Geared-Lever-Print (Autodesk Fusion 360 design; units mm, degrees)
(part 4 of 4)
sketch "Crossblock M3x20 cap head (-70, 1)" plane through (16, 0, 0) normal (1, 0, 0) x axis (0, 0, -1)
  circle C1 centre (-53.5, -70) radius 1.5
extrude "Extrude1" new body sketch "Crossblock M3x20 cap head (-70, 1)" along normal blind 20 bodies "HARDWARE Crossblock M3x20 cap head (-70, 1)"
work_plane "WorkPlane2" AlongDistance 36 ExtraOffset 0
sketch "Button head" plane through (36, 0, 0) normal (1, 0, 0) x axis (0, 0, -1)
  circle C1 centre (-53.5, -70) radius 2.75
extrude "Extrude2" add sketch "Button head" along normal blind 3
work_plane "WorkPlane1" AlongDistance 6.5 ExtraOffset 0
sketch "Rotor clamp M3x16 cap head" plane through (0, 6.5, 0) normal (0, 1, 0) x axis (1, 0, 0)
  circle C1 centre (0, -65) radius 1.5
extrude "Extrude1" new body sketch "Rotor clamp M3x16 cap head" along normal blind 16 bodies "HARDWARE Rotor clamp M3x16 cap head"
work_plane "WorkPlane2" AlongDistance 22.5 ExtraOffset 0
sketch "Button head" plane through (0, 22.5, 0) normal (0, 1, 0) x axis (1, 0, 0)
  circle C1 centre (0, -65) radius 2.75
extrude "Extrude2" add sketch "Button head" along normal blind 3
work_plane "WorkPlane20" AlongDistance 3.9 ExtraOffset 0
sketch "Restore axle bore after adding print feet" plane through (3.9, 0, 0) normal (1, 0, 0) x axis (0, 0, -1)
  circle C1 centre (-12, 0) radius 1.7
extrude "Extrude20" cut sketch "Restore axle bore after adding print feet" along normal blind 16.2
work_plane "WorkPlane21" AlongDistance 3.9 ExtraOffset 0
sketch "Restore nut installation recess after print foot" plane through (3.9, 0, 0) normal (1, 0, 0) x axis (0, 0, -1)
  line L1 (-14.9, 1.6743) -> (-12, 3.3486)
  line L2 (-14.9, -1.6743) -> (-14.9, 1.6743)
  line L3 (-12, -3.3486) -> (-14.9, -1.6743)
  line L4 (-9.1, -1.6743) -> (-12, -3.3486)
  line L5 (-9.1, 1.6743) -> (-9.1, -1.6743)
  line L6 (-12, 3.3486) -> (-9.1, 1.6743)
extrude "Extrude21" cut sketch "Restore nut installation recess after print foot" along normal blind 1.6
work_plane "WorkPlane3" AlongDistance 8 ExtraOffset 0
sketch "Retain one mm preload travel before head meets collar" plane through (8, 0, 0) normal (1, 0, 0) x axis (0, 0, -1)
  line L1 (-56, -51) -> (-56, -59)
  line L2 (-57.1, -51) -> (-56, -51)
  line L3 (-57.1, -59) -> (-57.1, -51)
  line L4 (-56, -59) -> (-57.1, -59)
extrude "Extrude3" cut sketch "Retain one mm preload travel before head meets collar" along normal blind 8
work_plane "WorkPlane63" AlongDistance 20.8 ExtraOffset 0
sketch "Clear stocked carriage screw tip beyond insert" plane through (0, 20.8, 0) normal (0, 1, 0) x axis (1, 0, 0)
  circle C1 centre (60.15, -65) radius 1.7
extrude "Extrude63" cut sketch "Clear stocked carriage screw tip beyond insert" along normal blind 0.6
work_plane "WorkPlane64" AlongDistance -21.4 ExtraOffset 0
sketch "Clear stocked carriage screw tip beyond insert (1)" plane through (0, -21.4, 0) normal (0, 1, 0) x axis (1, 0, 0)
  circle C1 centre (60.15, -65) radius 1.7
extrude "Extrude64" cut sketch "Clear stocked carriage screw tip beyond insert (1)" along normal blind 0.6
work_plane "WorkPlane22" AlongDistance -2.5 ExtraOffset 0
sketch "Support-free lower ramp under left inner-race pad" plane through (0, -2.5, 0) normal (0, 1, 0) x axis (1, 0, 0)
  line L1 (8.1, -9.5) -> (7, -9.5)
  line L2 (8.1, -10.7) -> (8.1, -9.5)
  line L3 (7, -9.6) -> (8.1, -10.7)
  line L4 (7, -9.5) -> (7, -9.6)
extrude "Extrude22" cut sketch "Support-free lower ramp under left inner-race pad" along normal blind 5
work_plane "WorkPlane23" AlongDistance -2.5 ExtraOffset 0
sketch "Support-free lower ramp under right inner-race pad" plane through (0, -2.5, 0) normal (0, 1, 0) x axis (1, 0, 0)
  line L1 (17, -9.5) -> (15.9, -9.5)
  line L2 (17, -9.6) -> (17, -9.5)
  line L3 (15.9, -10.7) -> (17, -9.6)
  line L4 (15.9, -9.5) -> (15.9, -10.7)
extrude "Extrude23" cut sketch "Support-free lower ramp under right inner-race pad" along normal blind 5
ground "Pin94"
ground "Pin95"
ground "Pin96"
ground "Pin97"
ground "Pin98"
ground "Pin99"
ground "Pin100"
ground "Pin101"
ground "Pin102"
ground "Pin103"
ground "Pin104"
ground "Pin105"
ground "Pin106"
ground "Pin107"
ground "Pin108"
ground "Pin109"
ground "Pin110"
ground "Pin111"
ground "Pin112"
ground "Pin113"
ground "Pin120"
ground "Pin121"
ground "Pin122"
ground "Pin123"
work_plane "WorkPlane65" AlongDistance 36 ExtraOffset 0
sketch "Remove Oldham carriage extensions" plane through (36, 0, 0) normal (1, 0, 0) x axis (0, 0, -1)
  line L1 (-46, 34) -> (-46, -34)
  line L2 (-84, 34) -> (-46, 34)
  line L3 (-84, -34) -> (-84, 34)
  line L4 (-46, -34) -> (-84, -34)
extrude "Extrude65" cut sketch "Remove Oldham carriage extensions" along normal blind 30.3
work_plane "WorkPlane66" AlongDistance 24 ExtraOffset 0
sketch "Upper geared sensor support" plane through (24, 0, 0) normal (1, 0, 0) x axis (0, 0, -1)
  line L1 (-78, -10) -> (-78, -23)
  line L2 (-126, -10) -> (-78, -10)
  line L3 (-126, -23) -> (-126, -10)
  line L4 (-78, -23) -> (-126, -23)
extrude "Extrude66" add sketch "Upper geared sensor support" along normal blind 10
work_plane "WorkPlane67" AlongDistance 24 ExtraOffset 0
sketch "Geared mount M3 insert from inboard face" plane through (24, 0, 0) normal (1, 0, 0) x axis (0, 0, -1)
  circle C1 centre (-110.15, -16) radius 2
extrude "Extrude67" cut sketch "Geared mount M3 insert from inboard face" along normal blind 6.8
work_plane "WorkPlane68" AlongDistance 30.7 ExtraOffset 0
sketch "Geared mount screw clearance" plane through (30.7, 0, 0) normal (1, 0, 0) x axis (0, 0, -1)
  circle C1 centre (-110.15, -16) radius 1.7
extrude "Extrude68" cut sketch "Geared mount screw clearance" along normal blind 3.4
work_plane "WorkPlane69" AlongDistance 24 ExtraOffset 0
sketch "Upper geared sensor support (1)" plane through (24, 0, 0) normal (1, 0, 0) x axis (0, 0, -1)
  line L1 (-78, 23) -> (-78, 10)
  line L2 (-126, 23) -> (-78, 23)
  line L3 (-126, 10) -> (-126, 23)
  line L4 (-78, 10) -> (-126, 10)
extrude "Extrude69" add sketch "Upper geared sensor support (1)" along normal blind 10
work_plane "WorkPlane70" AlongDistance 24 ExtraOffset 0
sketch "Geared mount M3 insert from inboard face (1)" plane through (24, 0, 0) normal (1, 0, 0) x axis (0, 0, -1)
  circle C1 centre (-110.15, 16) radius 2
extrude "Extrude70" cut sketch "Geared mount M3 insert from inboard face (1)" along normal blind 6.8
work_plane "WorkPlane71" AlongDistance 30.7 ExtraOffset 0
sketch "Geared mount screw clearance (1)" plane through (30.7, 0, 0) normal (1, 0, 0) x axis (0, 0, -1)
  circle C1 centre (-110.15, 16) radius 1.7
extrude "Extrude71" cut sketch "Geared mount screw clearance (1)" along normal blind 3.4
work_plane "WorkPlane1" AlongDistance -37.35 ExtraOffset 0
sketch "Continuous 12 mm journals" plane through (-37.35, 0, 0) normal (1, 0, 0) x axis (0, 0, -1)
  circle C1 centre (-65, 0) radius 6
extrude "Extrude1" new body sketch "Continuous 12 mm journals" along normal blind 74.7 bodies "P05G Shaft lower half"
work_plane "WorkPlane2" AlongDistance -23.8 ExtraOffset 0
sketch "Structural shaft" plane through (-23.8, 0, 0) normal (1, 0, 0) x axis (0, 0, -1)
  circle C1 centre (-65, 0) radius 8
extrude "Extrude2" add sketch "Structural shaft" along normal blind 47.6
work_plane "WorkPlane3" AlongDistance -23.9 ExtraOffset 0
sketch "Rotor D flat" plane through (-23.9, 0, 0) normal (1, 0, 0) x axis (0, 0, -1)
  line L1 (-56, 9) -> (-56, 6.5)
  line L2 (-74, 9) -> (-56, 9)
  line L3 (-74, 6.5) -> (-74, 9)
  line L4 (-56, 6.5) -> (-74, 6.5)
extrude "Extrude3" cut sketch "Rotor D flat" along normal blind 47.8
work_plane "WorkPlane4" AlongDistance 37.35 ExtraOffset 0
sketch "Retain axial shoulder" plane through (37.35, 0, 0) normal (1, 0, 0) x axis (0, 0, -1)
  circle C1 centre (-65, 0) radius 10
extrude "Extrude4" add sketch "Retain axial shoulder" along normal blind 3
work_plane "WorkPlane5" AlongDistance 40.35 ExtraOffset 0
sketch "Short D drive stub" plane through (40.35, 0, 0) normal (1, 0, 0) x axis (0, 0, -1)
  circle C1 centre (-65, 0) radius 4
extrude "Extrude5" add sketch "Short D drive stub" along normal blind 8
work_plane "WorkPlane6" AlongDistance 40.35 ExtraOffset 0
sketch "Drive stub D flat" plane through (40.35, 0, 0) normal (1, 0, 0) x axis (0, 0, -1)
  line L1 (-60, 5) -> (-60, 3.2)
  line L2 (-70, 5) -> (-60, 5)
  line L3 (-70, 3.2) -> (-70, 5)
  line L4 (-60, 3.2) -> (-70, 3.2)
extrude "Extrude6" cut sketch "Drive stub D flat" along normal blind 8.15
work_plane "WorkPlane7" AlongDistance -37.45 ExtraOffset 0
sketch "End retention insert" plane through (-37.45, 0, 0) normal (1, 0, 0) x axis (0, 0, -1)
  circle C1 centre (-65, 0) radius 2
extrude "Extrude7" cut sketch "End retention insert" along normal blind 6.8
work_plane "WorkPlane8" AlongDistance -6.8 ExtraOffset 0
sketch "Joining insert" plane through (0, -6.8, 0) normal (0, 1, 0) x axis (1, 0, 0)
  circle C1 centre (-15, -65) radius 2
extrude "Extrude8" cut sketch "Joining insert" along normal blind 6.9
work_plane "WorkPlane9" AlongDistance -0.1 ExtraOffset 0
sketch "Joining screw clearance" plane through (0, -0.1, 0) normal (0, 1, 0) x axis (1, 0, 0)
  circle C1 centre (-15, -65) radius 1.7
extrude "Extrude9" cut sketch "Joining screw clearance" along normal blind 6.7
work_plane "WorkPlane10" AlongDistance 3.5 ExtraOffset 0
sketch "Recessed cap head" plane through (0, 3.5, 0) normal (0, 1, 0) x axis (1, 0, 0)
  circle C1 centre (-15, -65) radius 3.1
extrude "Extrude10" cut sketch "Recessed cap head" along normal blind 3.1
work_plane "WorkPlane11" AlongDistance -6.8 ExtraOffset 0
sketch "Joining insert (1)" plane through (0, -6.8, 0) normal (0, 1, 0) x axis (1, 0, 0)
  circle C1 centre (15, -65) radius 2
extrude "Extrude11" cut sketch "Joining insert (1)" along normal blind 6.9
work_plane "WorkPlane12" AlongDistance -0.1 ExtraOffset 0
sketch "Joining screw clearance (1)" plane through (0, -0.1, 0) normal (0, 1, 0) x axis (1, 0, 0)
  circle C1 centre (15, -65) radius 1.7
extrude "Extrude12" cut sketch "Joining screw clearance (1)" along normal blind 6.7
work_plane "WorkPlane13" AlongDistance 3.5 ExtraOffset 0
sketch "Recessed cap head (1)" plane through (0, 3.5, 0) normal (0, 1, 0) x axis (1, 0, 0)
  circle C1 centre (15, -65) radius 3.1
extrude "Extrude13" cut sketch "Recessed cap head (1)" along normal blind 3.1
work_plane "WorkPlane14" AlongDistance -6.6 ExtraOffset 0
sketch "Retain alignment key pocket" plane through (-6.6, 0, 0) normal (1, 0, 0) x axis (0, 0, -1)
  line L1 (-61, 1.6) -> (-61, -1.6)
  line L2 (-69, 1.6) -> (-61, 1.6)
  line L3 (-69, -1.6) -> (-69, 1.6)
  line L4 (-61, -1.6) -> (-69, -1.6)
extrude "Extrude14" cut sketch "Retain alignment key pocket" along normal blind 3.2
work_plane "WorkPlane15" AlongDistance 3.4 ExtraOffset 0
sketch "Retain alignment key pocket (1)" plane through (3.4, 0, 0) normal (1, 0, 0) x axis (0, 0, -1)
  line L1 (-61, 1.6) -> (-61, -1.6)
  line L2 (-69, 1.6) -> (-61, 1.6)
  line L3 (-69, -1.6) -> (-69, 1.6)
  line L4 (-61, -1.6) -> (-69, -1.6)
extrude "Extrude15" cut sketch "Retain alignment key pocket (1)" along normal blind 3.2
split "Split1" bodies "P05G Shaft upper half"
work_plane "WorkPlane1" AlongDistance 40.5 ExtraOffset 0
sketch "Involute gear polygon m1.25 pressure20" plane through (40.5, 0, 0) normal (1, 0, 0) x axis (0, 0, -1)
  line L1 (-63.7058, 28.408) -> (-63.7058, 28.408)
  line L2 (-63.7507, 28.7619) -> (-63.7058, 28.408)
  line L3 (-63.8186, 29.1167) -> (-63.7507, 28.7619)
  line L4 (-63.9051, 29.4719) -> (-63.8186, 29.1167)
  line L5 (-64.0079, 29.8273) -> (-63.9051, 29.4719)
  line L6 (-64.1255, 30.1826) -> (-64.0079, 29.8273)
  line L7 (-64.257, 30.5378) -> (-64.1255, 30.1826)
  line L8 (-64.4015, 30.8926) -> (-64.257, 30.5378)
  line L9 (-64.5586, 31.2469) -> (-64.4015, 30.8926)
  line L10 (-65.4414, 31.2469) -> (-64.5586, 31.2469)
  line L11 (-65.5985, 30.8926) -> (-65.4414, 31.2469)
  line L12 (-65.743, 30.5378) -> (-65.5985, 30.8926)
  line L13 (-65.8745, 30.1826) -> (-65.743, 30.5378)
  line L14 (-65.9921, 29.8273) -> (-65.8745, 30.1826)
  line L15 (-66.0949, 29.4719) -> (-65.9921, 29.8273)
  line L16 (-66.1814, 29.1167) -> (-66.0949, 29.4719)
  line L17 (-66.2493, 28.7619) -> (-66.1814, 29.1167)
  line L18 (-66.2942, 28.408) -> (-66.2493, 28.7619)
  line L19 (-66.2942, 28.408) -> (-66.2942, 28.408)
  line L20 (-66.5771, 28.3937) -> (-66.2942, 28.408)
  line L21 (-66.8599, 28.3766) -> (-66.5771, 28.3937)
  line L22 (-67.1425, 28.3567) -> (-66.8599, 28.3766)
  line L23 (-67.4248, 28.3339) -> (-67.1425, 28.3567)
  line L24 (-67.4248, 28.3339) -> (-67.4248, 28.3339)
  line L25 (-67.5156, 28.6789) -> (-67.4248, 28.3339)
  line L26 (-67.6292, 29.0218) -> (-67.5156, 28.6789)
  line L27 (-67.7613, 29.3626) -> (-67.6292, 29.0218)
  line L28 (-67.9096, 29.7016) -> (-67.7613, 29.3626)
  line L29 (-68.0726, 30.0386) -> (-67.9096, 29.7016)
  line L30 (-68.2493, 30.3736) -> (-68.0726, 30.0386)
  line L31 (-68.4389, 30.7065) -> (-68.2493, 30.3736)
  line L32 (-68.6409, 31.0372) -> (-68.4389, 30.7065)
  line L33 (-69.5162, 30.9219) -> (-68.6409, 31.0372)
  line L34 (-69.6257, 30.5502) -> (-69.5162, 30.9219)
  line L35 (-69.7227, 30.1796) -> (-69.6257, 30.5502)
  line L36 (-69.8066, 29.8103) -> (-69.7227, 30.1796)
  line L37 (-69.8769, 29.4426) -> (-69.8066, 29.8103)
  line L38 (-69.9324, 29.0768) -> (-69.8769, 29.4426)
  line L39 (-69.9718, 28.7134) -> (-69.9324, 29.0768)
  line L40 (-69.9928, 28.3528) -> (-69.9718, 28.7134)
  line L41 (-69.9911, 27.9961) -> (-69.9928, 28.3528)
  line L42 (-69.9911, 27.9961) -> (-69.9911, 27.9961)
  line L43 (-70.2698, 27.945) -> (-69.9911, 27.9961)
  line L44 (-70.5479, 27.8911) -> (-70.2698, 27.945)
  line L45 (-70.8254, 27.8344) -> (-70.5479, 27.8911)
  line L46 (-71.1024, 27.775) -> (-70.8254, 27.8344)
  line L47 (-71.1024, 27.775) -> (-71.1024, 27.775)
  line L48 (-71.2374, 28.1052) -> (-71.1024, 27.775)
  line L49 (-71.3948, 28.4303) -> (-71.2374, 28.1052)
  line L50 (-71.5703, 28.751) -> (-71.3948, 28.4303)
  line L51 (-71.7616, 29.0677) -> (-71.5703, 28.751)
  line L52 (-71.9672, 29.3805) -> (-71.7616, 29.0677)
  line L53 (-72.1861, 29.6896) -> (-71.9672, 29.3805)
  line L54 (-72.4175, 29.9949) -> (-72.1861, 29.6896)
  line L55 (-72.6609, 30.2964) -> (-72.4175, 29.9949)
  line L56 (-73.5136, 30.0679) -> (-72.6609, 30.2964)
  line L57 (-73.5737, 29.6851) -> (-73.5136, 30.0679)
  line L58 (-73.6215, 29.305) -> (-73.5737, 29.6851)
  line L59 (-73.6565, 28.9279) -> (-73.6215, 29.305)
  line L60 (-73.6782, 28.5541) -> (-73.6565, 28.9279)
  line L61 (-73.6854, 28.1843) -> (-73.6782, 28.5541)
  line L62 (-73.6771, 27.8188) -> (-73.6854, 28.1843)
  line L63 (-73.6509, 27.4586) -> (-73.6771, 27.8188)
  line L64 (-73.6027, 27.1051) -> (-73.6509, 27.4586)
  line L65 (-73.6027, 27.1051) -> (-73.6027, 27.1051)
  line L66 (-73.8722, 27.018) -> (-73.6027, 27.1051)
  line L67 (-74.1409, 26.9283) -> (-73.8722, 27.018)
  line L68 (-74.4087, 26.8359) -> (-74.1409, 26.9283)
  line L69 (-74.6756, 26.7409) -> (-74.4087, 26.8359)
  line L70 (-74.6756, 26.7409) -> (-74.6756, 26.7409)
  line L71 (-74.8525, 27.0507) -> (-74.6756, 26.7409)
  line L72 (-75.051, 27.3524) -> (-74.8525, 27.0507)
  line L73 (-75.2669, 27.6474) -> (-75.051, 27.3524)
  line L74 (-75.4978, 27.9365) -> (-75.2669, 27.6474)
  line L75 (-75.7425, 28.2198) -> (-75.4978, 27.9365)
  line L76 (-75.9999, 28.4976) -> (-75.7425, 28.2198)
  line L77 (-76.2692, 28.7701) -> (-75.9999, 28.4976)
  line L78 (-76.5499, 29.0373) -> (-76.2692, 28.7701)
  line L79 (-77.3655, 28.6994) -> (-76.5499, 29.0373)
  line L80 (-77.375, 28.3121) -> (-77.3655, 28.6994)
  line L81 (-77.3728, 27.9289) -> (-77.375, 28.3121)
  line L82 (-77.3583, 27.5505) -> (-77.3728, 27.9289)
  line L83 (-77.331, 27.1771) -> (-77.3583, 27.5505)
  line L84 (-77.2899, 26.8095) -> (-77.331, 27.1771)
  line L85 (-77.2339, 26.4482) -> (-77.2899, 26.8095)
  line L86 (-77.1609, 26.0945) -> (-77.2339, 26.4482)
  line L87 (-77.067, 25.7503) -> (-77.1609, 26.0945)
  line L88 (-77.067, 25.7503) -> (-77.067, 25.7503)
  line L89 (-77.3229, 25.6288) -> (-77.067, 25.7503)
  line L90 (-77.5776, 25.5048) -> (-77.3229, 25.6288)
  line L91 (-77.831, 25.3783) -> (-77.5776, 25.5048)
  line L92 (-78.0832, 25.2492) -> (-77.831, 25.3783)
  line L93 (-78.0832, 25.2492) -> (-78.0832, 25.2492)
  line L94 (-78.299, 25.5332) -> (-78.0832, 25.2492)
  line L95 (-78.5352, 25.8065) -> (-78.299, 25.5332)
  line L96 (-78.7877, 26.0708) -> (-78.5352, 25.8065)
  line L97 (-79.0544, 26.3272) -> (-78.7877, 26.0708)
  line L98 (-79.334, 26.5762) -> (-79.0544, 26.3272)
  line L99 (-79.6254, 26.8181) -> (-79.334, 26.5762)
  line L100 (-79.928, 27.0531) -> (-79.6254, 26.8181)
  line L101 (-80.2412, 27.2813) -> (-79.928, 27.0531)
  line L102 (-81.0057, 26.8399) -> (-80.2412, 27.2813)
  line L103 (-80.9646, 26.4546) -> (-81.0057, 26.8399)
  line L104 (-80.9124, 26.075) -> (-80.9646, 26.4546)
  line L105 (-80.8487, 25.7017) -> (-80.9124, 26.075)
  line L106 (-80.7728, 25.3351) -> (-80.8487, 25.7017)
  line L107 (-80.6841, 24.9759) -> (-80.7728, 25.3351)
  line L108 (-80.5814, 24.6251) -> (-80.6841, 24.9759)
  line L109 (-80.4629, 24.2839) -> (-80.5814, 24.6251)
  line L110 (-80.3249, 23.955) -> (-80.4629, 24.2839)
  line L111 (-80.3249, 23.955) -> (-80.3249, 23.955)
  line L112 (-80.5627, 23.8011) -> (-80.3249, 23.955)
  line L113 (-80.799, 23.6449) -> (-80.5627, 23.8011)
  line L114 (-81.0338, 23.4864) -> (-80.799, 23.6449)
  line L115 (-81.2669, 23.3255) -> (-81.0338, 23.4864)
  line L116 (-81.2669, 23.3255) -> (-81.2669, 23.3255)
  line L117 (-81.518, 23.5789) -> (-81.2669, 23.3255)
  line L118 (-81.7879, 23.819) -> (-81.518, 23.5789)
  line L119 (-82.0727, 24.0481) -> (-81.7879, 23.819)
  line L120 (-82.3706, 24.2675) -> (-82.0727, 24.0481)
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extrude "Extrude1" new body sketch "Involute gear polygon m1.25 pressure20" along normal blind 8 bodies "G01 48T lever gear"
work_plane "WorkPlane2" AlongDistance 40.4 ExtraOffset 0
sketch "Shaft bore" plane through (40.4, 0, 0) normal (1, 0, 0) x axis (0, 0, -1)
  circle C1 centre (-65, 0) radius 4.1
extrude "Extrude2" cut sketch "Shaft bore" along normal blind 8.2
work_plane "WorkPlane3" AlongDistance 40.5 ExtraOffset 0
sketch "D key flat" plane through (40.5, 0, 0) normal (1, 0, 0) x axis (0, 0, -1)
  line L1 (-62, 4.3) -> (-62, 3.35)
  line L2 (-68, 4.3) -> (-62, 4.3)
  line L3 (-68, 3.35) -> (-68, 4.3)
  line L4 (-62, 3.35) -> (-68, 3.35)
extrude "Extrude3" add sketch "D key flat" along normal blind 8
work_plane "WorkPlane4" AlongDistance 40.4 ExtraOffset 0
sketch "Clamp slit outside operating mesh sector" plane through (40.4, 0, 0) normal (1, 0, 0) x axis (0, 0, -1)
  line L1 (-32, 0.2) -> (-32, -0.2)
  line L2 (-65, 0.2) -> (-32, 0.2)
  line L3 (-65, -0.2) -> (-65, 0.2)
  line L4 (-32, -0.2) -> (-65, -0.2)
extrude "Extrude4" cut sketch "Clamp slit outside operating mesh sector" along normal blind 8.2
work_plane "WorkPlane5" AlongDistance -8 ExtraOffset 0
sketch "Clamp heat-set insert pocket" plane through (0, -8, 0) normal (0, 1, 0) x axis (1, 0, 0)
  circle C1 centre (44.5, -57) radius 2
extrude "Extrude5" cut sketch "Clamp heat-set insert pocket" along normal blind 6.8
work_plane "WorkPlane6" AlongDistance -1.3 ExtraOffset 0
sketch "Clamp through screw" plane through (0, -1.3, 0) normal (0, 1, 0) x axis (1, 0, 0)
  circle C1 centre (44.5, -57) radius 1.7
extrude "Extrude6" cut sketch "Clamp through screw" along normal blind 6.4
work_plane "WorkPlane7" AlongDistance 5 ExtraOffset 0
sketch "Recessed clamp screw head and tool path" plane through (0, 5, 0) normal (0, 1, 0) x axis (1, 0, 0)
  circle C1 centre (44.5, -57) radius 3.1
extrude "Extrude7" cut sketch "Recessed clamp screw head and tool path" along normal blind 30
work_plane "WorkPlane1" AlongDistance -7 ExtraOffset 0
sketch "G01 48T lever gear clamp M3x12" plane through (0, -7, 0) normal (0, 1, 0) x axis (1, 0, 0)
  circle C1 centre (44.5, -57) radius 1.5
extrude "Extrude1" new body sketch "G01 48T lever gear clamp M3x12" along normal blind 12 bodies "HARDWARE G01 48T lever gear clamp M3x12"
work_plane "WorkPlane2" AlongDistance 5 ExtraOffset 0
sketch "Button head" plane through (0, 5, 0) normal (0, 1, 0) x axis (1, 0, 0)
  circle C1 centre (44.5, -57) radius 2.75
extrude "Extrude2" add sketch "Button head" along normal blind 3
work_plane "WorkPlane1" AlongDistance 40.5 ExtraOffset 0
sketch "Involute gear polygon m1.25 pressure20" plane through (40.5, 0, 0) normal (1, 0, 0) x axis (0, 0, -1)
  line L1 (-110.8997, 14.0754) -> (-110.8647, 13.4185)
  line L2 (-110.9494, 14.3425) -> (-110.8997, 14.0754)
  line L3 (-111.0295, 14.6076) -> (-110.9494, 14.3425)
  line L4 (-111.1304, 14.8711) -> (-111.0295, 14.6076)
  line L5 (-111.2488, 15.1329) -> (-111.1304, 14.8711)
  line L6 (-111.383, 15.3927) -> (-111.2488, 15.1329)
  line L7 (-111.5317, 15.6505) -> (-111.383, 15.3927)
  line L8 (-111.6943, 15.9059) -> (-111.5317, 15.6505)
  line L9 (-111.87, 16.1587) -> (-111.6943, 15.9059)
  line L10 (-112.6708, 16.0533) -> (-111.87, 16.1587)
  line L11 (-112.7751, 15.7636) -> (-112.6708, 16.0533)
  line L12 (-112.866, 15.4748) -> (-112.7751, 15.7636)
  line L13 (-112.943, 15.1873) -> (-112.866, 15.4748)
  line L14 (-113.0053, 14.9016) -> (-112.943, 15.1873)
  line L15 (-113.0519, 14.6181) -> (-113.0053, 14.9016)
  line L16 (-113.0812, 14.3375) -> (-113.0519, 14.6181)
  line L17 (-113.0899, 14.0607) -> (-113.0812, 14.3375)
  line L18 (-113.0688, 13.7899) -> (-113.0899, 14.0607)
  line L19 (-112.9326, 13.1462) -> (-113.0688, 13.7899)
  line L20 (-113.2814, 13.0676) -> (-112.9326, 13.1462)
  line L21 (-113.6279, 12.9796) -> (-113.2814, 13.0676)
  line L22 (-113.9719, 12.8825) -> (-113.6279, 12.9796)
  line L23 (-114.3133, 12.7763) -> (-113.9719, 12.8825)
  line L24 (-114.5171, 13.4018) -> (-114.3133, 12.7763)
  line L25 (-114.6343, 13.6468) -> (-114.5171, 13.4018)
  line L26 (-114.7803, 13.8822) -> (-114.6343, 13.6468)
  line L27 (-114.9459, 14.1106) -> (-114.7803, 13.8822)
  line L28 (-115.128, 14.3328) -> (-114.9459, 14.1106)
  line L29 (-115.3249, 14.5491) -> (-115.128, 14.3328)
  line L30 (-115.5353, 14.7596) -> (-115.3249, 14.5491)
  line L31 (-115.7584, 14.9642) -> (-115.5353, 14.7596)
  line L32 (-115.9936, 15.1629) -> (-115.7584, 14.9642)
  line L33 (-116.7398, 14.8539) -> (-115.9936, 15.1629)
  line L34 (-116.7656, 14.547) -> (-116.7398, 14.8539)
  line L35 (-116.7786, 14.2446) -> (-116.7656, 14.547)
  line L36 (-116.7786, 13.947) -> (-116.7786, 14.2446)
  line L37 (-116.7649, 13.6548) -> (-116.7786, 13.947)
  line L38 (-116.7365, 13.3689) -> (-116.7649, 13.6548)
  line L39 (-116.6921, 13.0903) -> (-116.7365, 13.3689)
  line L40 (-116.6289, 12.8206) -> (-116.6921, 13.0903)
  line L41 (-116.5385, 12.5645) -> (-116.6289, 12.8206)
  line L42 (-116.2403, 11.9781) -> (-116.5385, 12.5645)
  line L43 (-116.5568, 11.8118) -> (-116.2403, 11.9781)
  line L44 (-116.8688, 11.6372) -> (-116.5568, 11.8118)
  line L45 (-117.176, 11.4544) -> (-116.8688, 11.6372)
  line L46 (-117.4782, 11.2634) -> (-117.176, 11.4544)
  line L47 (-117.837, 11.8148) -> (-117.4782, 11.2634)
  line L48 (-118.0136, 12.0212) -> (-117.837, 11.8148)
  line L49 (-118.2155, 12.2108) -> (-118.0136, 12.0212)
  line L50 (-118.4346, 12.3885) -> (-118.2155, 12.2108)
  line L51 (-118.668, 12.556) -> (-118.4346, 12.3885)
  line L52 (-118.9141, 12.714) -> (-118.668, 12.556)
  line L53 (-119.1718, 12.8628) -> (-118.9141, 12.714)
  line L54 (-119.4403, 13.0028) -> (-119.1718, 12.8628)
  line L55 (-119.7189, 13.1339) -> (-119.4403, 13.0028)
  line L56 (-120.3597, 12.6422) -> (-119.7189, 13.1339)
  line L57 (-120.3052, 12.3391) -> (-120.3597, 12.6422)
  line L58 (-120.2395, 12.0436) -> (-120.3052, 12.3391)
  line L59 (-120.1625, 11.7561) -> (-120.2395, 12.0436)
  line L60 (-120.0736, 11.4775) -> (-120.1625, 11.7561)
  line L61 (-119.9722, 11.2087) -> (-120.0736, 11.4775)
  line L62 (-119.8572, 10.951) -> (-119.9722, 11.2087)
  line L63 (-119.7264, 10.7069) -> (-119.8572, 10.951)
  line L64 (-119.5727, 10.4829) -> (-119.7264, 10.7069)
  line L65 (-119.1329, 9.9937) -> (-119.5727, 10.4829)
  line L66 (-119.3956, 9.7512) -> (-119.1329, 9.9937)
  line L67 (-119.6517, 9.5017) -> (-119.3956, 9.7512)
  line L68 (-119.9012, 9.2456) -> (-119.6517, 9.5017)
  line L69 (-120.1437, 8.9829) -> (-119.9012, 9.2456)
  line L70 (-120.6329, 9.4227) -> (-120.1437, 8.9829)
  line L71 (-120.8569, 9.5764) -> (-120.6329, 9.4227)
  line L72 (-121.101, 9.7072) -> (-120.8569, 9.5764)
  line L73 (-121.3587, 9.8222) -> (-121.101, 9.7072)
  line L74 (-121.6275, 9.9236) -> (-121.3587, 9.8222)
  line L75 (-121.9061, 10.0125) -> (-121.6275, 9.9236)
  line L76 (-122.1936, 10.0895) -> (-121.9061, 10.0125)
  line L77 (-122.4891, 10.1552) -> (-122.1936, 10.0895)
  line L78 (-122.7922, 10.2097) -> (-122.4891, 10.1552)
  line L79 (-123.2839, 9.5689) -> (-122.7922, 10.2097)
  line L80 (-123.1528, 9.2903) -> (-123.2839, 9.5689)
  line L81 (-123.0128, 9.0218) -> (-123.1528, 9.2903)
  line L82 (-122.864, 8.7641) -> (-123.0128, 9.0218)
  line L83 (-122.706, 8.518) -> (-122.864, 8.7641)
  line L84 (-122.5385, 8.2846) -> (-122.706, 8.518)
  line L85 (-122.3608, 8.0655) -> (-122.5385, 8.2846)
  line L86 (-122.1712, 7.8636) -> (-122.3608, 8.0655)
  line L87 (-121.9648, 7.687) -> (-122.1712, 7.8636)
  line L88 (-121.4134, 7.3282) -> (-121.9648, 7.687)
  line L89 (-121.6044, 7.026) -> (-121.4134, 7.3282)
  line L90 (-121.7872, 6.7187) -> (-121.6044, 7.026)
  line L91 (-121.9618, 6.4068) -> (-121.7872, 6.7187)
  line L92 (-122.1281, 6.0903) -> (-121.9618, 6.4068)
  line L93 (-122.7145, 6.3885) -> (-122.1281, 6.0903)
  line L94 (-122.9706, 6.4789) -> (-122.7145, 6.3885)
  line L95 (-123.2403, 6.5421) -> (-122.9706, 6.4789)
  line L96 (-123.5189, 6.5865) -> (-123.2403, 6.5421)
  line L97 (-123.8048, 6.6149) -> (-123.5189, 6.5865)
  line L98 (-124.097, 6.6286) -> (-123.8048, 6.6149)
  line L99 (-124.3946, 6.6286) -> (-124.097, 6.6286)
  line L100 (-124.697, 6.6156) -> (-124.3946, 6.6286)
  line L101 (-125.0039, 6.5898) -> (-124.697, 6.6156)
  line L102 (-125.3129, 5.8436) -> (-125.0039, 6.5898)
  line L103 (-125.1142, 5.6084) -> (-125.3129, 5.8436)
  line L104 (-124.9096, 5.3853) -> (-125.1142, 5.6084)
  line L105 (-124.6991, 5.1749) -> (-124.9096, 5.3853)
  line L106 (-124.4828, 4.978) -> (-124.6991, 5.1749)
  line L107 (-124.2606, 4.7959) -> (-124.4828, 4.978)
  line L108 (-124.0322, 4.6303) -> (-124.2606, 4.7959)
  line L109 (-123.7968, 4.4843) -> (-124.0322, 4.6303)
  line L110 (-123.5518, 4.3671) -> (-123.7968, 4.4843)
  line L111 (-122.9263, 4.1633) -> (-123.5518, 4.3671)
  line L112 (-123.0325, 3.8219) -> (-122.9263, 4.1633)
  line L113 (-123.1296, 3.4779) -> (-123.0325, 3.8219)
  line L114 (-123.2176, 3.1314) -> (-123.1296, 3.4779)
  line L115 (-123.2962, 2.7826) -> (-123.2176, 3.1314)
  line L116 (-123.9399, 2.9188) -> (-123.2962, 2.7826)
  line L117 (-124.2107, 2.9399) -> (-123.9399, 2.9188)
  line L118 (-124.4875, 2.9312) -> (-124.2107, 2.9399)
  line L119 (-124.7681, 2.9019) -> (-124.4875, 2.9312)
  line L120 (-125.0516, 2.8553) -> (-124.7681, 2.9019)
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extrude "Extrude1" new body sketch "Involute gear polygon m1.25 pressure20" along normal blind 8 bodies "G02 24T sensor pinion"
work_plane "WorkPlane2" AlongDistance 40.4 ExtraOffset 0
sketch "Shaft bore" plane through (40.4, 0, 0) normal (1, 0, 0) x axis (0, 0, -1)
  circle C1 centre (-110.15, 0) radius 3.1
extrude "Extrude2" cut sketch "Shaft bore" along normal blind 8.2
work_plane "WorkPlane3" AlongDistance 40.4 ExtraOffset 0
sketch "Sensor bushing end relief" plane through (40.4, 0, 0) normal (1, 0, 0) x axis (0, 0, -1)
  circle C1 centre (-110.15, 0) radius 3.6
extrude "Extrude3" cut sketch "Sensor bushing end relief" along normal blind 0.9
work_plane "WorkPlane4" AlongDistance 40.4 ExtraOffset 0
sketch "Clamp slit outside operating mesh sector" plane through (40.4, 0, 0) normal (1, 0, 0) x axis (0, 0, -1)
  line L1 (-110.15, 0.2) -> (-110.15, -0.2)
  line L2 (-127, 0.2) -> (-110.15, 0.2)
  line L3 (-127, -0.2) -> (-127, 0.2)
  line L4 (-110.15, -0.2) -> (-127, -0.2)
extrude "Extrude4" cut sketch "Clamp slit outside operating mesh sector" along normal blind 8.2
work_plane "WorkPlane5" AlongDistance -8 ExtraOffset 0
sketch "Clamp heat-set insert pocket" plane through (0, -8, 0) normal (0, 1, 0) x axis (1, 0, 0)
  circle C1 centre (44.5, -118.15) radius 2
work_plane "WorkPlane6" AlongDistance -1.3 ExtraOffset 0
sketch "Clamp through screw" plane through (0, -1.3, 0) normal (0, 1, 0) x axis (1, 0, 0)
  circle C1 centre (44.5, -118.15) radius 1.7
work_plane "WorkPlane7" AlongDistance 5 ExtraOffset 0
sketch "Recessed clamp screw head and tool path" plane through (0, 5, 0) normal (0, 1, 0) x axis (1, 0, 0)
  circle C1 centre (44.5, -118.15) radius 3.1
work_plane "WorkPlane1" AlongDistance 34 ExtraOffset 0
sketch "Geared sensor panel" plane through (34, 0, 0) normal (1, 0, 0) x axis (0, 0, -1)
  line L1 (-96, 23) -> (-96, -23)
  line L2 (-126, 23) -> (-96, 23)
  line L3 (-126, -23) -> (-126, 23)
  line L4 (-96, -23) -> (-126, -23)
extrude "Extrude1" new body sketch "Geared sensor panel" along normal blind 3 bodies "G03 Radially adjustable potentiometer panel"
work_plane "WorkPlane2" AlongDistance 33.9 ExtraOffset 0
sketch "Provisional M7 bushing" plane through (33.9, 0, 0) normal (1, 0, 0) x axis (0, 0, -1)
  circle C1 centre (-110.15, 0) radius 3.6
extrude "Extrude2" cut sketch "Provisional M7 bushing" along normal blind 3.2
work_plane "WorkPlane3" AlongDistance 33.9 ExtraOffset 0
sketch "Vertical mesh adjustment slot" plane through (33.9, 0, 0) normal (1, 0, 0) x axis (0, 0, -1)
  line L1 (-108.95, -14.3) -> (-108.95, -17.7)
  line L2 (-111.35, -14.3) -> (-108.95, -14.3)
  line L3 (-111.35, -17.7) -> (-111.35, -14.3)
  line L4 (-108.95, -17.7) -> (-111.35, -17.7)
extrude "Extrude3" cut sketch "Vertical mesh adjustment slot" along normal blind 3.2
work_plane "WorkPlane1" AlongDistance 25 ExtraOffset 0
sketch "Geared panel M3x12 -16" plane through (25, 0, 0) normal (1, 0, 0) x axis (0, 0, -1)
  circle C1 centre (-110.15, -16) radius 1.5
extrude "Extrude1" new body sketch "Geared panel M3x12 -16" along normal blind 12 bodies "HARDWARE Geared panel M3x12 -16"
work_plane "WorkPlane2" AlongDistance 37 ExtraOffset 0
sketch "Button head" plane through (37, 0, 0) normal (1, 0, 0) x axis (0, 0, -1)
  circle C1 centre (-110.15, -16) radius 2.75
extrude "Extrude2" add sketch "Button head" along normal blind 3
work_plane "WorkPlane4" AlongDistance 33.9 ExtraOffset 0
sketch "Vertical mesh adjustment slot (1)" plane through (33.9, 0, 0) normal (1, 0, 0) x axis (0, 0, -1)
  line L1 (-108.95, 17.7) -> (-108.95, 14.3)
  line L2 (-111.35, 17.7) -> (-108.95, 17.7)
  line L3 (-111.35, 14.3) -> (-111.35, 17.7)
  line L4 (-108.95, 14.3) -> (-111.35, 14.3)
extrude "Extrude4" cut sketch "Vertical mesh adjustment slot (1)" along normal blind 3.2
work_plane "WorkPlane1" AlongDistance 25 ExtraOffset 0
sketch "Geared panel M3x12 16" plane through (25, 0, 0) normal (1, 0, 0) x axis (0, 0, -1)
  circle C1 centre (-110.15, 16) radius 1.5
extrude "Extrude1" new body sketch "Geared panel M3x12 16" along normal blind 12 bodies "HARDWARE Geared panel M3x12 16"
work_plane "WorkPlane2" AlongDistance 37 ExtraOffset 0
sketch "Button head" plane through (37, 0, 0) normal (1, 0, 0) x axis (0, 0, -1)
  circle C1 centre (-110.15, 16) radius 2.75
extrude "Extrude2" add sketch "Button head" along normal blind 3
work_plane "WorkPlane1" AlongDistance 20 ExtraOffset 0
sketch "Provisional sensor body" plane through (20, 0, 0) normal (1, 0, 0) x axis (0, 0, -1)
  line L1 (-105.4, 4.75) -> (-105.4, -4.75)
  line L2 (-114.9, 4.75) -> (-105.4, 4.75)
  line L3 (-114.9, -4.75) -> (-114.9, 4.75)
  line L4 (-105.4, -4.75) -> (-114.9, -4.75)
extrude "Extrude1" new body sketch "Provisional sensor body" along normal blind 14 bodies "REFERENCE Geared RK097 provisional envelope"
work_plane "WorkPlane2" AlongDistance 34 ExtraOffset 0
sketch "Provisional bushing" plane through (34, 0, 0) normal (1, 0, 0) x axis (0, 0, -1)
  circle C1 centre (-110.15, 0) radius 3.5
extrude "Extrude2" add sketch "Provisional bushing" along normal blind 7
work_plane "WorkPlane3" AlongDistance 41 ExtraOffset 0
sketch "Provisional 12 mm exposed shaft" plane through (41, 0, 0) normal (1, 0, 0) x axis (0, 0, -1)
  circle C1 centre (-110.15, 0) radius 3
extrude "Extrude3" add sketch "Provisional 12 mm exposed shaft" along normal blind 12
work_plane "WorkPlane1" AlongDistance 37 ExtraOffset 0
sketch "Geared RK097 supplied washer ASSUMED" plane through (37, 0, 0) normal (1, 0, 0) x axis (0, 0, -1)
  circle C1 centre (-110.15, 0) radius 6
extrude "Extrude1" new body sketch "Geared RK097 supplied washer ASSUMED" along normal blind 0.5 bodies "HARDWARE Geared RK097 supplied washer ASSUMED"
work_plane "WorkPlane2" AlongDistance 36.9 ExtraOffset 0
sketch "Washer clearance" plane through (36.9, 0, 0) normal (1, 0, 0) x axis (0, 0, -1)
  circle C1 centre (-110.15, 0) radius 3.6
extrude "Extrude2" cut sketch "Washer clearance" along normal blind 0.7
work_plane "WorkPlane1" AlongDistance 37.5 ExtraOffset 0
sketch "Geared RK097 supplied nut ASSUMED" plane through (37.5, 0, 0) normal (1, 0, 0) x axis (0, 0, -1)
  line L1 (-115.65, 3.1754) -> (-110.15, 6.3509)
  line L2 (-115.65, -3.1754) -> (-115.65, 3.1754)
  line L3 (-110.15, -6.3509) -> (-115.65, -3.1754)
  line L4 (-104.65, -3.1754) -> (-110.15, -6.3509)
  line L5 (-104.65, 3.1754) -> (-104.65, -3.1754)
  line L6 (-110.15, 6.3509) -> (-104.65, 3.1754)
extrude "Extrude1" new body sketch "Geared RK097 supplied nut ASSUMED" along normal blind 2 bodies "HARDWARE Geared RK097 supplied nut ASSUMED"
work_plane "WorkPlane2" AlongDistance 37.4 ExtraOffset 0
sketch "Thread envelope" plane through (37.4, 0, 0) normal (1, 0, 0) x axis (0, 0, -1)
  circle C1 centre (-110.15, 0) radius 3.5
extrude "Extrude2" cut sketch "Thread envelope" along normal blind 2.2
work_plane "WorkPlane8" AlongDistance -7 ExtraOffset 0
sketch "Revised clamp insert pocket" plane through (0, -7, 0) normal (0, 1, 0) x axis (1, 0, 0)
  circle C1 centre (44.5, -117.65) radius 2
extrude "Extrude8" cut sketch "Revised clamp insert pocket" along normal blind 6.8
work_plane "WorkPlane9" AlongDistance -0.3 ExtraOffset 0
sketch "Revised clamp screw clearance" plane through (0, -0.3, 0) normal (0, 1, 0) x axis (1, 0, 0)
  circle C1 centre (44.5, -117.65) radius 1.7
extrude "Extrude9" cut sketch "Revised clamp screw clearance" along normal blind 5.4
work_plane "WorkPlane10" AlongDistance 5 ExtraOffset 0
sketch "Revised recessed clamp head" plane through (0, 5, 0) normal (0, 1, 0) x axis (1, 0, 0)
  circle C1 centre (44.5, -117.65) radius 3.1
extrude "Extrude10" cut sketch "Revised recessed clamp head" along normal blind 30
work_plane "WorkPlane1" AlongDistance -7 ExtraOffset 0
sketch "G02 24T sensor pinion clamp M3x12" plane through (0, -7, 0) normal (0, 1, 0) x axis (1, 0, 0)
  circle C1 centre (44.5, -117.65) radius 1.5
extrude "Extrude1" new body sketch "G02 24T sensor pinion clamp M3x12" along normal blind 12 bodies "HARDWARE G02 24T sensor pinion clamp M3x12"
work_plane "WorkPlane2" AlongDistance 5 ExtraOffset 0
sketch "Button head" plane through (0, 5, 0) normal (0, 1, 0) x axis (1, 0, 0)
  circle C1 centre (44.5, -117.65) radius 2.75
extrude "Extrude2" add sketch "Button head" along normal blind 3
work_plane "WorkPlane11" AlongDistance 40.4 ExtraOffset 0
sketch "Open support-free clamp tool channel" plane through (40.4, 0, 0) normal (1, 0, 0) x axis (0, 0, -1)
  line L1 (-114.55, 18) -> (-114.55, 5)
  line L2 (-120.75, 18) -> (-114.55, 18)
  line L3 (-120.75, 5) -> (-120.75, 18)
  line L4 (-114.55, 5) -> (-120.75, 5)
extrude "Extrude11" cut sketch "Open support-free clamp tool channel" along normal blind 8.2
position "Position1"
work_plane "WorkPlane5" AlongDistance 33.9 ExtraOffset 0
sketch "Clearance and travel for M3 panel screw" plane through (33.9, 0, 0) normal (1, 0, 0) x axis (0, 0, -1)
  line L1 (-107.25, -14.3) -> (-107.25, -17.7)
  line L2 (-113.05, -14.3) -> (-107.25, -14.3)
  line L3 (-113.05, -17.7) -> (-113.05, -14.3)
  line L4 (-107.25, -17.7) -> (-113.05, -17.7)
extrude "Extrude5" cut sketch "Clearance and travel for M3 panel screw" along normal blind 3.2
work_plane "WorkPlane6" AlongDistance 33.9 ExtraOffset 0
sketch "Clearance and travel for M3 panel screw (1)" plane through (33.9, 0, 0) normal (1, 0, 0) x axis (0, 0, -1)
  line L1 (-107.25, 17.7) -> (-107.25, 14.3)
  line L2 (-113.05, 17.7) -> (-107.25, 17.7)
  line L3 (-113.05, 14.3) -> (-113.05, 17.7)
  line L4 (-107.25, 14.3) -> (-113.05, 14.3)
extrude "Extrude6" cut sketch "Clearance and travel for M3 panel screw (1)" along normal blind 3.2
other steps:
create_component "CreateComponent1"
create_component "CreateComponent2"
create_component "CreateComponent3"
create_component "CreateComponent4"
create_component "CreateComponent5"
create_component "CreateComponent7"
create_component "CreateComponent8"
create_component "CreateComponent9"
create_component "CreateComponent10"
create_component "CreateComponent11"
create_component "CreateComponent12"
create_component "CreateComponent13"
create_component "CreateComponent14"
create_component "CreateComponent16"
create_component "CreateComponent28"
create_component "CreateComponent29"
create_component "CreateComponent49"
create_component "CreateComponent89"
create_component "CreateComponent90"
create_component "CreateComponent140"
create_component "CreateComponent141"
create_component "CreateComponent142"
create_component "CreateComponent143"
create_component "CreateComponent144"
create_component "CreateComponent145"
create_component "CreateComponent146"
create_component "CreateComponent147"
create_component "CreateComponent148"
create_component "CreateComponent149"
create_component "CreateComponent150"
create_component "CreateComponent151"
create_component "CreateComponent152"
create_component "CreateComponent153"
create_component "CreateComponent154"
create_component "CreateComponent155"
create_component "CreateComponent156"
create_component "CreateComponent157"
create_component "CreateComponent158"
create_component "CreateComponent159"
create_component "CreateComponent160"
create_component "CreateComponent161"
create_component "CreateComponent171"
create_component "CreateComponent172"
create_component "CreateComponent173"
create_component "CreateComponent174"
create_component "CreateComponent175"
create_component "CreateComponent176"
create_component "CreateComponent177"
create_component "CreateComponent178"
create_component "CreateComponent179"
create_component "CreateComponent180"
create_component "CreateComponent181"
create_component "CreateComponent182"
create_component "CreateComponent183"
create_component "CreateComponent184"
create_component "CreateComponent185"
create_component "CreateComponent186"
create_component "CreateComponent187"
create_component "CreateComponent188"
create_component "CreateComponent190"
create_component "CreateComponent191"
create_component "CreateComponent192"
create_component "CreateComponent193"
create_component "CreateComponent194"
create_component "CreateComponent195"
create_component "CreateComponent196"
named bodies: "P01 Left rail sideplate", "P02G Right plate with upper sensor supports", "P03 Left flanged journal bush", "P04 Right flanged journal bush", "P06 Shaft retaining cap", "P07 Integral lever rotor and cam carrier", "P08 Cam 7 gates - stable endpoints", "P08 Cam 5 gates - stable endpoints", "P08 Cam 3 gates - stable endpoints", "P09 Grip insert half", "P10 Grip screw half", "P11 Forked roller follower", "P13 Spring reaction crossblock", "P21 Follower left axial spacer", "P22 Follower right axial spacer", "HARDWARE Roller axle M3 nut", "P23 Left rotor thrust spacer", "P24 Right rotor thrust spacer", "HARDWARE Rail M5x14 DIN912 (-30, -1)", "HARDWARE Rail M5x14 DIN912 (-30, 1)", "HARDWARE Rail M5x14 DIN912 (30, -1)", "HARDWARE Rail M5x14 DIN912 (30, 1)", "P25 Captured printed pivot lower half", "P26 Captured printed pivot upper half", "HARDWARE Grip M3x20 cap head 180", "HARDWARE Grip M3x20 cap head 190", "HARDWARE Stop M3x20 cap head -1", "HARDWARE Stop M3 plain captive nut -1", "HARDWARE Stop M3x20 cap head 1", "HARDWARE Stop M3 plain captive nut 1", "HARDWARE 623ZZ roller bearing at 8", "HARDWARE 623ZZ roller bearing at 12", "P27 Printed guide sleeve 4", "HARDWARE Cup guide M3x12 4", "P27 Printed guide sleeve 20", "HARDWARE Cup guide M3x12 20", "P14 Captive spring cup for 9 mm spring", "P15 Recessed preload limit collar 1 mm", "HARDWARE Preload M3x20 cap head", "REFERENCE Stock spring OD9 wire1 free20 - rate and solid height assumed", "HARDWARE Shaft joining M3x8 -15", "HARDWARE Shaft joining M3x8 15", "P28 Shaft alignment key -5", "P28 Shaft alignment key 5", "HARDWARE Main shaft cap M3x8 cap head", "HARDWARE Cam M3x10 cap head -45", "HARDWARE Cam M3x10 cap head 0", "HARDWARE Cam M3x10 cap head 45", "HARDWARE Roller axle M3x20 cap head", "HARDWARE Crossblock M3x20 cap head (-62, -1)", "HARDWARE Crossblock M3x20 cap head (-62, 1)", "HARDWARE Crossblock M3x20 cap head (-70, -1)", "HARDWARE Crossblock M3x20 cap head (-70, 1)", "HARDWARE Rotor clamp M3x16 cap head", "P05G Shaft lower half", "P05G Shaft upper half", "G01 48T lever gear", "HARDWARE G01 48T lever gear clamp M3x12", "G02 24T sensor pinion", "G03 Radially adjustable potentiometer panel"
